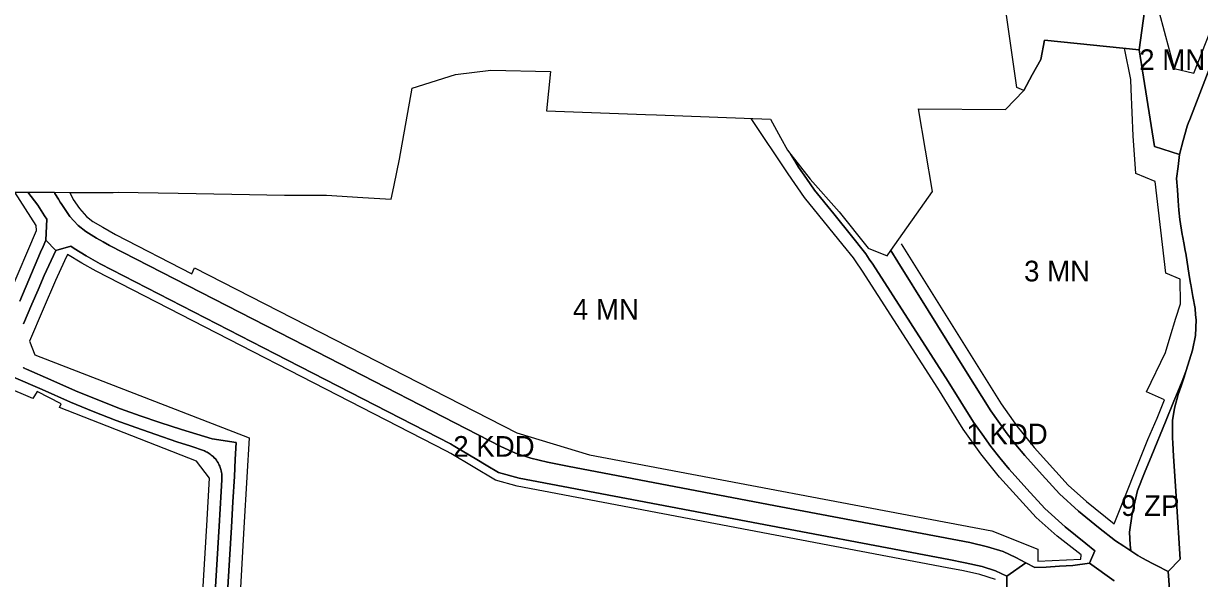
# Model space of a CAD drawing. Extents: x 7423432 to 7425824, y 5537848 to 5539677.
# Drawn here: x 7423720 to 7424289, y 5538773 to 5539041 of the extents above; entities that cross this region are included whole.
import ezdxf

# ---------------------------------------------------------------- set-up
doc = ezdxf.new("R2010")
doc.units = 0
for name, color, linetype in [('linie_rozgraniczajace', 7, 'Continuous'), ('linie_zabudowy_nieprzekraczalne', 7, 'Continuous'), ('oznaczenia_przeznaczen', 7, 'Continuous')]:
    doc.layers.add(name, color=color, linetype=linetype)

msp = doc.modelspace()

# ---------------------------------------------------------------- linework, layer by layer
at = {"layer": 'linie_rozgraniczajace'}
for points in [[(7424262.54, 5539047.33), (7424259.92, 5539028.68), (7424214.13, 5539033.28), (7424212.25, 5539024), (7424208.15, 5539016.49), (7424204.05, 5539008.98), (7424200.68, 5539010.35), (7424193.55, 5539060.17)], [(7424273.98, 5538776.07), (7424279.74, 5538782.02), (7424277.96, 5538810.11), (7424276.57, 5538831.92), (7424276.17, 5538838.2), (7424276.11, 5538840.9), (7424276.04, 5538843.6), (7424276.09, 5538849.26), (7424277.01, 5538855.24), (7424278.81, 5538861.78), (7424280.19, 5538865.85), (7424281.49, 5538869.68), (7424282.69, 5538873.44), (7424285.81, 5538883.21), (7424287.18, 5538890.41), (7424287.49, 5538897.95), (7424287.26, 5538900.37), (7424287.06, 5538903.42), (7424285.98, 5538909.23), (7424284.89, 5538915.03), (7424284.8, 5538915.59), (7424284.02, 5538920.53), (7424283.69, 5538922.61), (7424282.49, 5538930.19), (7424282.26, 5538931.39), (7424281.68, 5538934.41), (7424280.87, 5538938.63), (7424280.77, 5538939.25), (7424279.57, 5538946.51), (7424279.19, 5538951.02), (7424278.8, 5538955.52), (7424278.43, 5538960.91), (7424278.05, 5538966.3), (7424278.73, 5538972.09), (7424279.41, 5538977.88), (7424281.3, 5538984.77), (7424283.18, 5538991.67), (7424283.82, 5538993.42), (7424284.42, 5538994.92), (7424294.97, 5539022.17)], [(7424247.87, 5538771.6), (7424235.92, 5538780.12), (7424238.5, 5538786.21), (7424234.04, 5538789.65), (7424229.03, 5538793.71), (7424224.03, 5538797.79), (7424214.22, 5538806.57), (7424205.57, 5538816.15), (7424196.91, 5538825.73), (7424192.45, 5538831.19), (7424188.01, 5538836.65), (7424183.86, 5538842.53), (7424179.71, 5538848.4), (7424173.56, 5538858.24), (7424167.4, 5538868.08), (7424149.17, 5538896.45), (7424130.94, 5538924.83), (7424129.21, 5538927.35), (7424127.48, 5538929.88), (7424126.88, 5538930.71), (7424126.28, 5538931.55), (7424121.31, 5538937.84), (7424111.99, 5538949.28), (7424102.67, 5538960.72), (7424098.83, 5538966.27), (7424095, 5538971.82), (7424093.13, 5538974.88), (7424091.27, 5538977.95), (7424100.56, 5538965.99), (7424114.63, 5538950.18), (7424128.73, 5538932.59), (7424137.82, 5538928.99), (7424139.61, 5538931.52), (7424143.05, 5538926), (7424157.75, 5538902.45), (7424175.88, 5538873.38), (7424188.04, 5538853.94), (7424195.97, 5538842.7), (7424200.24, 5538837.48), (7424204.49, 5538832.25), (7424212.89, 5538822.96), (7424221.29, 5538813.67), (7424230.52, 5538805.39), (7424240.28, 5538797.46), (7424248.5, 5538791.01), (7424252.53, 5538788.35), (7424255.92, 5538786.12), (7424259.28, 5538783.89), (7424261.52, 5538782.66), (7424266, 5538780.2), (7424268.24, 5538778.97), (7424273.98, 5538776.07), (7424275.09, 5538761.16)], [(7423703.32, 5538959.73), (7423721.75, 5538959.68), (7423726.59, 5538953.38), (7423729.74, 5538948.27), (7423730.85, 5538946.63), (7423730.36, 5538936.49), (7423729.05, 5538933.41), (7423727.87, 5538930.65), (7423717.78, 5538907.05)], [(7423717.78, 5538907.05), (7423727.87, 5538930.65), (7423729.05, 5538933.41), (7423730.36, 5538936.49), (7423735.18, 5538931.56), (7423729.58, 5538919.41), (7423726.61, 5538912.45), (7423723.63, 5538905.49), (7423719.57, 5538895.95)], [(7423719.57, 5538895.95), (7423723.63, 5538905.49), (7423726.61, 5538912.45), (7423729.58, 5538919.41), (7423735.18, 5538931.56), (7423742.52, 5538933.65), (7423744.09, 5538932.42), (7423747, 5538930.66), (7423749.91, 5538928.89), (7423753.3, 5538926.99), (7423756.69, 5538925.08), (7423841.52, 5538881.51), (7423926.34, 5538837.93), (7423928.55, 5538836.64), (7423939.14, 5538830.32), (7423943.69, 5538827.61), (7423949.7, 5538824.02), (7423959.58, 5538821.28), (7424063.64, 5538801.59), (7424167.69, 5538781.89), (7424175.71, 5538780.38), (7424183.89, 5538778.49), (7424190.39, 5538776.42), (7424195.78, 5538773.91), (7424195.8, 5538768.54)], [(7423714.77, 5538870.18), (7423728.57, 5538864.14), (7423742.37, 5538858.1), (7423753.38, 5538853.64), (7423764.4, 5538849.18), (7423774.04, 5538845.84), (7423783.67, 5538842.51), (7423793.83, 5538838.94), (7423800.56, 5538836.71), (7423807.3, 5538834.47), (7423807.66, 5538834.27), (7423808.07, 5538834.07), (7423808.56, 5538833.82), (7423809.08, 5538833.52), (7423809.51, 5538833.25), (7423810.06, 5538832.87), (7423810.53, 5538832.51), (7423810.99, 5538832.12), (7423811.44, 5538831.72), (7423811.95, 5538831.2), (7423812.5, 5538830.58), (7423813, 5538829.94), (7423813.41, 5538829.37), (7423813.79, 5538828.75), (7423814.14, 5538828.13), (7423814.39, 5538827.61), (7423814.62, 5538827.09), (7423814.87, 5538826.45), (7423815.05, 5538825.93), (7423815.2, 5538825.42), (7423815.35, 5538824.8), (7423815.49, 5538824.07), (7423815.59, 5538823.4), (7423815.65, 5538822.73), (7423815.67, 5538822.19), (7423815.67, 5538821.4), (7423815.6, 5538820.49), (7423815.28, 5538814.86), (7423814.8, 5538806.42), (7423814.32, 5538797.99), (7423813.4, 5538782.03), (7423812.47, 5538766.07)], [(7423812.47, 5538766.07), (7423813.4, 5538782.03), (7423814.32, 5538797.99), (7423814.8, 5538806.42), (7423815.28, 5538814.86), (7423815.6, 5538820.49), (7423815.67, 5538821.4), (7423815.67, 5538822.19), (7423815.65, 5538822.73), (7423815.59, 5538823.4), (7423815.49, 5538824.07), (7423815.35, 5538824.8), (7423815.2, 5538825.42), (7423815.05, 5538825.93), (7423814.87, 5538826.45), (7423814.62, 5538827.09), (7423814.39, 5538827.61), (7423814.14, 5538828.13), (7423813.79, 5538828.75), (7423813.41, 5538829.37), (7423813, 5538829.94), (7423812.5, 5538830.58), (7423811.95, 5538831.2), (7423811.44, 5538831.72), (7423810.99, 5538832.12), (7423810.53, 5538832.51), (7423810.06, 5538832.87), (7423809.51, 5538833.25), (7423809.08, 5538833.52), (7423808.56, 5538833.82), (7423808.07, 5538834.07), (7423807.66, 5538834.27), (7423807.3, 5538834.47), (7423800.56, 5538836.71), (7423793.83, 5538838.94), (7423783.67, 5538842.51), (7423774.04, 5538845.84), (7423764.4, 5538849.18), (7423753.38, 5538853.64), (7423742.37, 5538858.1), (7423728.57, 5538864.14), (7423714.77, 5538870.18)], [(7423818.46, 5538765.81), (7423819.39, 5538781.73), (7423820.31, 5538797.65), (7423821.01, 5538809.88), (7423821.7, 5538822.11), (7423822.16, 5538830.31), (7423822.63, 5538838.5), (7423810.92, 5538840.3), (7423803.49, 5538842.6), (7423796.06, 5538844.9), (7423785.56, 5538848.2), (7423776.03, 5538851.5), (7423766.51, 5538854.8), (7423755.6, 5538859.21), (7423744.7, 5538863.63), (7423732.84, 5538868.82), (7423720.99, 5538874.02), (7423720.24, 5538874.4), (7423720.17, 5538874.44), (7423720, 5538874.54), (7423719.82, 5538874.64), (7423719.65, 5538874.75), (7423719.48, 5538874.86)], [(7423719.48, 5538874.86), (7423719.65, 5538874.75), (7423719.82, 5538874.64), (7423720, 5538874.54), (7423720.17, 5538874.44), (7423720.24, 5538874.4), (7423720.99, 5538874.02), (7423732.84, 5538868.82), (7423744.7, 5538863.63), (7423755.6, 5538859.21), (7423766.51, 5538854.8), (7423776.03, 5538851.5), (7423785.56, 5538848.2), (7423796.06, 5538844.9), (7423803.49, 5538842.6), (7423810.92, 5538840.3), (7423822.63, 5538838.5), (7423822.16, 5538830.31), (7423821.7, 5538822.11), (7423821.01, 5538809.88), (7423820.31, 5538797.65), (7423819.39, 5538781.73), (7423818.46, 5538765.81), (7423818.02, 5538750.81)], [(7424195.8, 5538768.54), (7424195.78, 5538773.91), (7424205.03, 5538780.36), (7424209.45, 5538778.06), (7424214.84, 5538778.24), (7424221.28, 5538778.66), (7424227.72, 5538779.09), (7424235.92, 5538780.12), (7424247.87, 5538771.6)], [(7424289.56, 5538645.57), (7424288.93, 5538649.59), (7424288.29, 5538653.61), (7424287.58, 5538661.77), (7424286.87, 5538669.93), (7424286.6, 5538674.45), (7424286.34, 5538678.98), (7424286.05, 5538688.49), (7424285.76, 5538698), (7424285.04, 5538708.5), (7424284.31, 5538718.99), (7424283.49, 5538729.65), (7424282.66, 5538740.31), (7424282.26, 5538745.8), (7424281.86, 5538751.29), (7424275.09, 5538761.16), (7424273.98, 5538776.07)]]:
    msp.add_lwpolyline(points, dxfattribs=at)
for points in [[(7424259.92, 5539028.68), (7424262.54, 5539047.33), (7424267.1, 5539058.52), (7424305.52, 5539049.42), (7424294.97, 5539022.17), (7424284.42, 5538994.92), (7424283.82, 5538993.42), (7424283.18, 5538991.67), (7424281.3, 5538984.77), (7424279.41, 5538977.88), (7424267.33, 5538981.83)], [(7424139.61, 5538931.52), (7424159.84, 5538960.08), (7424153.09, 5539000.01), (7424195.15, 5538999.8), (7424204.05, 5539008.98), (7424208.15, 5539016.49), (7424212.25, 5539024), (7424214.13, 5539033.28), (7424259.92, 5539028.68), (7424267.33, 5538981.83), (7424279.41, 5538977.88), (7424278.73, 5538972.09), (7424278.05, 5538966.3), (7424278.43, 5538960.91), (7424278.8, 5538955.52), (7424279.19, 5538951.02), (7424279.57, 5538946.51), (7424280.77, 5538939.25), (7424280.87, 5538938.63), (7424281.68, 5538934.41), (7424282.26, 5538931.39), (7424282.49, 5538930.19), (7424283.69, 5538922.61), (7424284.02, 5538920.53), (7424284.8, 5538915.59), (7424284.89, 5538915.03), (7424285.98, 5538909.23), (7424287.06, 5538903.42), (7424287.26, 5538900.37), (7424287.49, 5538897.95), (7424287.18, 5538890.41), (7424285.81, 5538883.21), (7424282.69, 5538873.44), (7424280.67, 5538868.33), (7424279.58, 5538865.53), (7424278.45, 5538862.75), (7424276.75, 5538858.59), (7424272.63, 5538848.5), (7424266.06, 5538832.45), (7424262.57, 5538823.87), (7424259.08, 5538815.29), (7424256.56, 5538804.07), (7424255.29, 5538795.1), (7424255.38, 5538792.07), (7424255.48, 5538789.04), (7424255.92, 5538786.12), (7424252.53, 5538788.35), (7424248.5, 5538791.01), (7424240.28, 5538797.46), (7424230.52, 5538805.39), (7424221.29, 5538813.67), (7424212.89, 5538822.96), (7424204.49, 5538832.25), (7424200.24, 5538837.48), (7424195.97, 5538842.7), (7424188.04, 5538853.94), (7424175.88, 5538873.38), (7424157.75, 5538902.45), (7424143.05, 5538926)], [(7423734.38, 5538959.65), (7423742.32, 5538959.63), (7423758.92, 5538959.59), (7423763.02, 5538959.58), (7423765.5, 5538959.66), (7423794.47, 5538959.18), (7423820.54, 5538958.74), (7423845.94, 5538958.31), (7423849.63, 5538958.25), (7423866.26, 5538958.35), (7423883.98, 5538957.19), (7423897.73, 5538956.3), (7423898.03, 5538957.76), (7423899.08, 5538963.1), (7423901.76, 5538975.63), (7423907.8, 5539010.1), (7423928.83, 5539016.73), (7423945.91, 5539018.71), (7423974.82, 5539018.19), (7423972.87, 5538999.05), (7424020.83, 5538997.35), (7424026.22, 5538997.11), (7424081.4, 5538995.03), (7424086.23, 5538986.23), (7424089.6, 5538980.09), (7424091.27, 5538977.95), (7424093.13, 5538974.88), (7424095, 5538971.82), (7424098.83, 5538966.27), (7424102.67, 5538960.72), (7424111.99, 5538949.28), (7424121.31, 5538937.84), (7424126.28, 5538931.55), (7424126.88, 5538930.71), (7424127.48, 5538929.88), (7424129.21, 5538927.35), (7424130.94, 5538924.83), (7424149.17, 5538896.45), (7424167.4, 5538868.08), (7424173.56, 5538858.24), (7424179.71, 5538848.4), (7424183.86, 5538842.53), (7424188.01, 5538836.65), (7424192.45, 5538831.19), (7424196.91, 5538825.73), (7424205.57, 5538816.15), (7424214.22, 5538806.57), (7424224.03, 5538797.79), (7424229.03, 5538793.71), (7424234.04, 5538789.65), (7424238.5, 5538786.21), (7424235.92, 5538780.12), (7424227.72, 5538779.09), (7424221.28, 5538778.66), (7424214.84, 5538778.24), (7424209.45, 5538778.06), (7424205.03, 5538780.36), (7424200.2, 5538782.88), (7424197.12, 5538784.31), (7424194.03, 5538785.75), (7424186.54, 5538788.14), (7424177.96, 5538790.12), (7424080.47, 5538808.58), (7423982.99, 5538827.03), (7423978.14, 5538828.04), (7423973.3, 5538829.05), (7423969.32, 5538829.98), (7423965.33, 5538830.91), (7423957.92, 5538833.37), (7423950.69, 5538836.67), (7423855.98, 5538885.32), (7423761.26, 5538933.98), (7423758.11, 5538935.75), (7423754.95, 5538937.52), (7423752.37, 5538939.09), (7423749.79, 5538940.66), (7423746.09, 5538943.56), (7423744.03, 5538945.8), (7423741.96, 5538948.03), (7423738.14, 5538953.69), (7423737.36, 5538954.96), (7423736.49, 5538956.38), (7423734.83, 5538959.06)], [(7423721.75, 5538959.68), (7423734.38, 5538959.65), (7423734.83, 5538959.06), (7423736.49, 5538956.38), (7423737.36, 5538954.96), (7423738.14, 5538953.69), (7423741.96, 5538948.03), (7423744.03, 5538945.8), (7423746.09, 5538943.56), (7423749.79, 5538940.66), (7423752.37, 5538939.09), (7423754.95, 5538937.52), (7423758.11, 5538935.75), (7423761.26, 5538933.98), (7423855.98, 5538885.32), (7423950.69, 5538836.67), (7423957.92, 5538833.37), (7423965.33, 5538830.91), (7423969.32, 5538829.98), (7423973.3, 5538829.05), (7423978.14, 5538828.04), (7423982.99, 5538827.03), (7424080.47, 5538808.58), (7424177.96, 5538790.12), (7424186.54, 5538788.14), (7424194.03, 5538785.75), (7424197.12, 5538784.31), (7424200.2, 5538782.88), (7424205.03, 5538780.36), (7424195.78, 5538773.91), (7424190.39, 5538776.42), (7424183.89, 5538778.49), (7424175.71, 5538780.38), (7424167.69, 5538781.89), (7424063.64, 5538801.59), (7423959.58, 5538821.28), (7423949.7, 5538824.02), (7423943.69, 5538827.61), (7423939.14, 5538830.32), (7423928.55, 5538836.64), (7423926.34, 5538837.93), (7423841.52, 5538881.51), (7423756.69, 5538925.08), (7423753.3, 5538926.99), (7423749.91, 5538928.89), (7423747, 5538930.66), (7423744.09, 5538932.42), (7423742.52, 5538933.65), (7423735.18, 5538931.56), (7423730.36, 5538936.49), (7423730.85, 5538946.63), (7423729.74, 5538948.27), (7423726.59, 5538953.38)], [(7424255.48, 5538789.04), (7424255.38, 5538792.07), (7424255.29, 5538795.1), (7424256.56, 5538804.07), (7424259.08, 5538815.29), (7424262.57, 5538823.87), (7424266.06, 5538832.45), (7424272.63, 5538848.5), (7424276.75, 5538858.59), (7424278.45, 5538862.75), (7424279.58, 5538865.53), (7424280.67, 5538868.33), (7424282.69, 5538873.44), (7424281.49, 5538869.68), (7424280.19, 5538865.85), (7424278.81, 5538861.78), (7424277.01, 5538855.24), (7424276.09, 5538849.26), (7424276.04, 5538843.6), (7424276.11, 5538840.9), (7424276.17, 5538838.2), (7424276.57, 5538831.92), (7424277.96, 5538810.11), (7424279.74, 5538782.02), (7424273.98, 5538776.07), (7424268.24, 5538778.97), (7424266, 5538780.2), (7424261.52, 5538782.66), (7424259.28, 5538783.89), (7424255.92, 5538786.12)]]:
    msp.add_lwpolyline(points, close=True, dxfattribs=at)
at = {"layer": 'linie_zabudowy_nieprzekraczalne'}
for points in [[(7424272.25, 5539057.3), (7424269.66, 5539046.74), (7424276.81, 5539019.63), (7424286.43, 5539017.31), (7424299.87, 5539051.45), (7424304.2, 5539064.48), (7424306.06, 5539072.43), (7424308.31, 5539085.76), (7424309.6, 5539132.87), (7424297.04, 5539218.5), (7424282.3, 5539305.84), (7424276.47, 5539305.07), (7424267.67, 5539364.7), (7424261.54, 5539410.77)], [(7424279.7, 5538917.56), (7424272.86, 5538920.58), (7424267.62, 5538964.83), (7424258.28, 5538968.69), (7424257.08, 5538987.03), (7424256.12, 5539009.55), (7424255.91, 5539014.3), (7424252.85, 5539029.39)], [(7423742.1, 5538959.63), (7423743.71, 5538956.17), (7423746.68, 5538951.76), (7423750.17, 5538947.99), (7423753.21, 5538945.6), (7423757.98, 5538942.71), (7423764.1, 5538939.26), (7423801.18, 5538920.22), (7423802.47, 5538923.13), (7423958.55, 5538843.32), (7423993.76, 5538832.65), (7424188.62, 5538795.74), (7424210.87, 5538786.92), (7424210.8, 5538781.15), (7424231.63, 5538782.05), (7424231.87, 5538784.22), (7424231.87, 5538784.22), (7424220.13, 5538793.22), (7424209.98, 5538802.32), (7424192.35, 5538821.82), (7424183.22, 5538833.02), (7424174.72, 5538845.08), (7424162.34, 5538864.87), (7424125.94, 5538921.51), (7424122.57, 5538926.43), (7424121.49, 5538927.93), (7424116.63, 5538934.08), (7424097.87, 5538957.11), (7424089.96, 5538968.55), (7424072, 5538995.39)], [(7423725.86, 5538941.12), (7423725.76, 5538943.54), (7423715.34, 5538959.7)], [(7423699.64, 5538879.89), (7423725.86, 5538941.12)], [(7424144.7, 5538934.69), (7424180.97, 5538876.56), (7424193.04, 5538857.26), (7424200.76, 5538846.33), (7424209.05, 5538836.16), (7424225.53, 5538817.93), (7424234.42, 5538809.96), (7424247.88, 5538799.12), (7424264.12, 5538839.96), (7424268.62, 5538850.38), (7424272.13, 5538859.16), (7424263.54, 5538863.1), (7424272.68, 5538882.05), (7424275.01, 5538889.63), (7424277.66, 5538898.68), (7424279.89, 5538905.74), (7424279.7, 5538917.56)], [(7424190.32, 5538772.33), (7424182.83, 5538774.63), (7424174.89, 5538776.46), (7424166.95, 5538777.96), (7423958.67, 5538817.39), (7423948.15, 5538820.3), (7423926.52, 5538833.2), (7423924.42, 5538834.43), (7423754.8, 5538921.56), (7423747.89, 5538925.44), (7423740.91, 5538929.54), (7423739.47, 5538926.54), (7423735.07, 5538916.97), (7423729.15, 5538903.13), (7423722.53, 5538887.64)], [(7423722.53, 5538887.64), (7423725.03, 5538880.97), (7423828.88, 5538840.9), (7423827.69, 5538821.77), (7423826.3, 5538797.3), (7423824.46, 5538765.54)], [(7423806.47, 5538766.33), (7423808.33, 5538798.34), (7423809.63, 5538821.23), (7423803.34, 5538829.61), (7423736.99, 5538855.51), (7423736.99, 5538855.51), (7423737.79, 5538857.34), (7423726.15, 5538863.2), (7423724.03, 5538859.79), (7423696.4, 5538871.64)]]:
    msp.add_lwpolyline(points, dxfattribs=at)

# ---------------------------------------------------------------- texts
at = {"layer": 'oznaczenia_przeznaczen'}
for s, p in [('2 MN', (7424259.94, 5539018.86)), ('3 MN', (7424204.18, 5538916.54)), ('4 MN', (7423985.68, 5538898.01)), ('1 KDD', (7424176.24, 5538837.69)), ('2 KDD', (7423927.74, 5538831.67)), ('9 ZP', (7424251.17, 5538803.02))]:
    msp.add_text(s, height=10, dxfattribs=at).set_placement(p)

doc.saveas('drawing.dxf')
